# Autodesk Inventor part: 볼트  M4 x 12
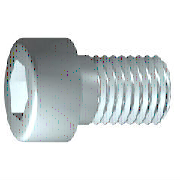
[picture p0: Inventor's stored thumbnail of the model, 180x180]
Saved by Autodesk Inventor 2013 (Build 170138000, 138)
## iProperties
IsCustomPart: 0
Created: 2015-12
Part Number: 볼트  M4 x 12
Material: 스테인리스강
Description: 6각머리 태핑 나사
Document SubType Name: Modeling
Standard: KS B 1003
Designer: mdu
Standards Organization: KS
Language: ko-KR
Size Designation: M 4 x 12
Categories: <MemberInstance><Categories><Category DisplayName="조임쇠" InternalName="e4da775c-781d-43d5-af7c-5136215cf5a6" Mnemonic="FSTN"><Category DisplayName="볼트" InternalN
Density: 1 g/cm^3
Mass: 0.284306 g
Surface Area: 3.30853 cm^2
Volume: 0.284306 cm^3
Author: mdu
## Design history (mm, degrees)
sketch "스케치1"
  geometry: L1 (-1, 0)-(10, 0); L2 (10, 0)-(10, 2); L3 (10, 2)-(1.75, 2); L4 (1.75, 2)-(1.32, 2); L5 (1.32, 2)-(0, 2); L6 (0, 2)-(0, 3.5); L7 (0, 3.5)-(-4, 3.5); L8 (-4, 3.5)-(-4, 1.732); L9 (-4, 1.732)-(-2, 1.732); L10 (-2, 1.732)-(-1, 0); L11 (-7.2, 0)-(15.2, 0) reference; L12 (0, -0.7)-(0, 4.2) reference; L13 (1.75, 2)-(0, 2)
  constraints: 22 end point, 6 parallel, 2 collinear, 2 perpendicular, 1 horizontal, 1 point on line
  dimensions: "d1" = 8.25 distance from line of L3.end L2 (= GEL); "d2" = 0.42952 distance of L4.end L3.end (computed from GAL); "d3" = 4 distance between parallel lines of L8 L6 (= KOH); "d4" = 2 distance of L8.end L9.end (= INTI); "d5" = 60 deg angle of L10 L1; "d6" = 4 diameter of L3 L1 (= GD); "d7" = 4 diameter of L5 L1 (= BDM); "d8" = 3.4641 diameter of L9 L1 (= 1.1547 x SW); "d9" = 7 diameter of L7 L1 (= KOD); "d26" = 10 distance between parallel lines of L12 L2 (= NLG)
revolve "본체" sketch "스케치1" stored, may be unused: angle "d10" = 90 deg
sketch "스케치2"
  geometry: L1 (0, -4.9)-(0, 4.9) reference; L2 (-4.9, 0)-(4.9, 0) reference; L3 (1.732, 0)-(0.866, -1.5); L4 (0.866, -1.5)-(-0.866, -1.5); L5 (-0.866, -1.5)-(-1.732, 0); L6 (-1.732, 0)-(-0.866, 1.5); L7 (-0.866, 1.5)-(0.866, 1.5); L8 (0.866, 1.5)-(1.732, 0); 2 further points
  constraints: 12 end point, 1 coincident, 1 horizontal alignment, 1 point on line, 12 other
extrude "슬롯" join sketch "스케치2" stored distance "d11" = 10; taper "d12" = 0 deg
workplane "Work Plane1"
fillet "Fillet2" dims "d30" = 0.1 (= R)
body "Solid1"
fillet "모깎기1" dims "d17" = 0.4 (= RR)
feature "스레드" dims "d13" = 8.25 (= GEL), "d14" = 0
chamfer "모따기1" distance "d15" = 0.42941 (= -0.5 x SPD + 0.5 x GD); stored, may be unused: second distance "d16" = 0.42941 (= GUL), angle "d27" = 45 deg
other parameters: "GD" = 4 (= NND) [user parameter; used in 2 equation terms], "NLG" = 10 [user parameter; used in 1 equation term], "GEL" = 8.25 [user parameter; used in 2 equation terms], "KOD" = 7 [user parameter; used in 1 equation term], "KOH" = 4 [user parameter; used in 1 equation term], "INTI" = 2 [user parameter; used in 1 equation term], "GAL" = 0.42941 (= 0.61345 x PTC) [user parameter; used in 1 equation term], "GUL" = 0.42941 (= 0.61345 x PTC) [user parameter; used in 1 equation term], "BDM" = 4 (= NND) [user parameter; used in 1 equation term], "SW" = 3 [user parameter; used in 2 equation terms], "RR" = 0.4 [user parameter; used in 1 equation term], "SPD" = 3.14117 (= NND - 1.2269 x PTC) [user parameter; used in 1 equation term], "d19" = 0, "d28" = 0, "d29" = 0, "R" = 0.1 [user parameter; used in 1 equation term], "PHH" = 0.2 [user parameter], "GD1" = 3.14117 (= THREADDIA - 1.2269 x PTC) [user parameter], "THREADDIA" = 4 [user parameter; used in 1 equation term], "FAWI" = 45 deg [user parameter], "TPU" = 14.28571 (computed from PTC) [user parameter], "PTC" = 0.7 [user parameter; used in 5 equation terms], "NND" = 4 [user parameter; used in 3 equation terms], "TOA" = 30 deg [user parameter], "E0" = 3.465 (= 1.155 x SW) [user parameter]
